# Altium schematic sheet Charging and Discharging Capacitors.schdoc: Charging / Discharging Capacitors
size A4; Organization: Altium Limited; Address1: L3, 12a Rodborough Rd; Address2: Frenchs Forest; Address3: NSW; Address4: Australia 2086; DocumentNumber: 1; SheetNumber: 1; SheetTotal: 1
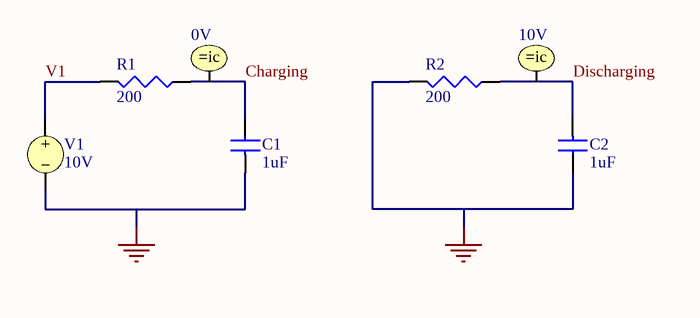
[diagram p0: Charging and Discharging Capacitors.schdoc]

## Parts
C1  1uF
C2  1uF
IC1  0V
IC2  10V
R1  200
R2  200
V1  10V

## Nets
GND: C1.1 C2.2 R2.1(TOP) V1.2
Charging: C1.2 IC1.1 R1.2(BOT)
Discharging: C2.1 IC2.1 R2.2(BOT)
V1: R1.1(TOP) V1.1

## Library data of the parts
C1 C2 = CAP: Capacitor
IC1 IC2 = .IC: Initial Condition
R1 R2 = RES: Resistor
V1 = VSRC: Voltage Source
